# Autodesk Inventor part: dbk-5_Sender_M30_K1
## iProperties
Shininess: 20.0
Length Units: 11269
Angle Units: 11279
Time Units: 11290
Mass Units: 11283
Length Display Precision: 2
Angle Display Precision: 2
Company: Microsonic
Part Number: dbk-5_Sender_M30_K1
Material: Nichtrostender Stahl - 440C
Document SubType Name: Modellieren
Description: dbk-5/Sender/M30/K1
Checked By: Alves
Created: 2005-08
Designer: Ohle
Manufacturer: Standard
Standards Organization: Custom
Density: 0.0
Volumn: 0.0
Area: 0.0
PropertySet Name: Model Information
Control State: 0
Master: False
Checked Out: False
Last Check In By: ohle
Last Check In Date: 2005-08-23
BESTELLNUMMER: dbk-5/Sender/M30/K1
ME: ST
Title: wms Sensoren
Author: Ohle
Comments: keine Bemerkung
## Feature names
1. dbk-5 Sender [Revolution]
2. Litzen Sender [Extrusion]
